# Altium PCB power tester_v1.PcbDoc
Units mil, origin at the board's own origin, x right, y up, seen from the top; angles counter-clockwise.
Board outline 3937.01 x 5944.88 mil, 2 copper layers (Top Layer, Bottom Layer); 152 components, 159 nets, 630 pads, 0 vias.
Unrouted connection lines stored in the file: 446.
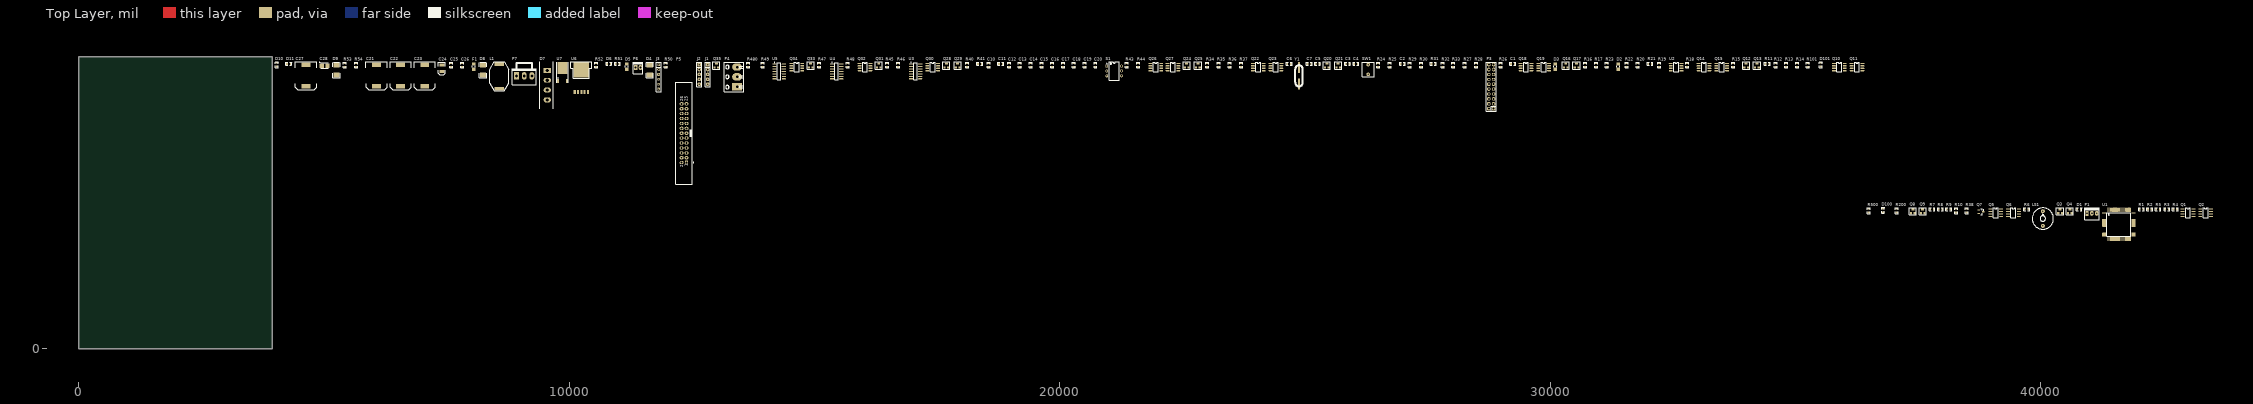
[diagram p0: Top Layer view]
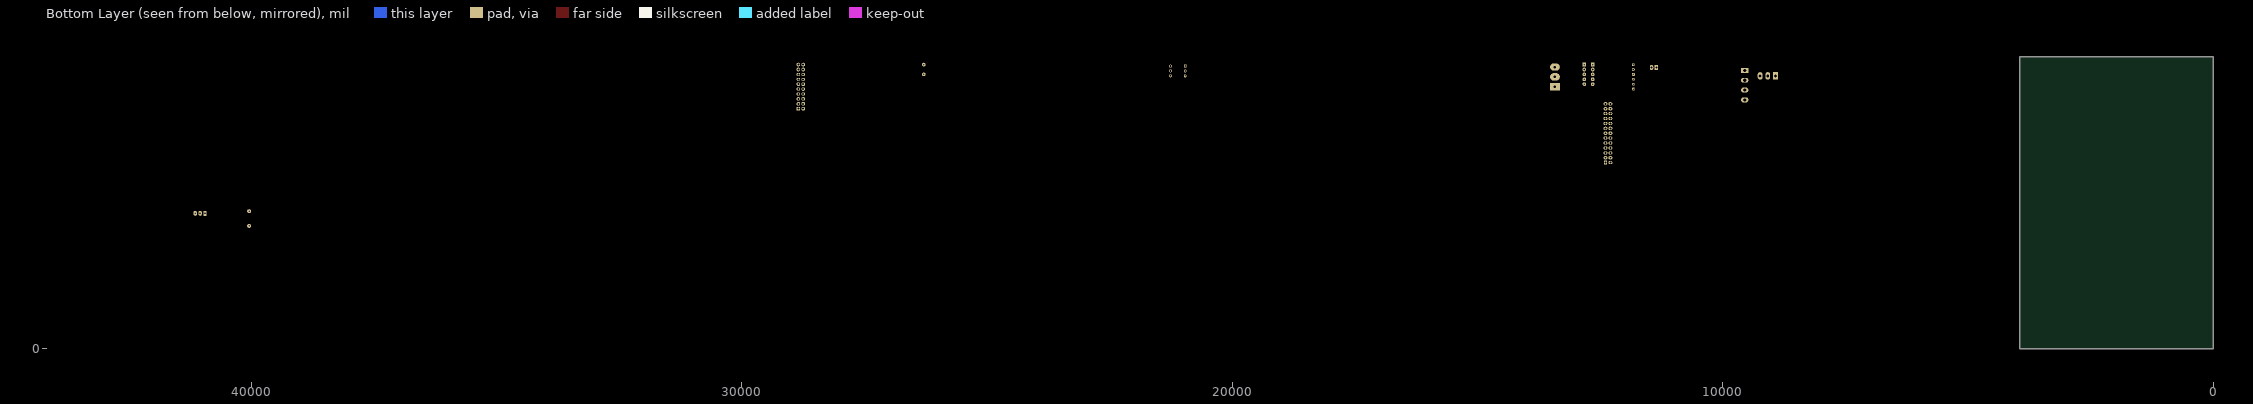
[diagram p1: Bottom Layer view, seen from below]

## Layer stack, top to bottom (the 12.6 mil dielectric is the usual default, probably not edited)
Top Solder: solder mask 0.4, Solder Resist, Dk 3.5
Top Layer: signal copper 1.4
Dielectric1: dielectric 12.6, FR-4, Dk 4.8
Bottom Layer: signal copper 1.4
Bottom Solder: solder mask 0.4, Solder Resist, Dk 3.5

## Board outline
0,0 0,5944.88 3937.01,5944.88 3937.01,0

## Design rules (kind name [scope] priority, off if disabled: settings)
Clearance Clearance_1 [(InNet('GND') OR InNet('SGND')) vs (InNet('GND') OR InNet('SGND'))] p1: gap=0
Clearance [All] p2: gap=7.5
ComponentClearance [All] p1 off: gap=10 collisioncheckmode=3 verticalgap=10 showdistances=FALSE
Height [All] p1 off: minheight=0 maxheight=1000 prefheight=500
HoleSize [All] p1 off: absolutevalues=TRUE maxlimit=100 minlimit=1 maxpercent=80.000 minpercent=20.000
HoleToHoleClearance [All] p1 off: gap=10 allowstackedmicrovias=TRUE
LayerPairs [All] p1 off: enforce=TRUE
MinimumSolderMaskSliver [All] p1 off: minsoldermaskwidth=10
NetAntennae [All] p1 off: netantennaetolerance=0
PolygonConnect [All] p1: connectstyle=Direct reliefconductorwidth=10 reliefentries=4 polygonreliefangle="90 Angle" airgapwidth=10
RoutingVias [All] p1: holewidth=28 width=50 viastyle="Through Hole" minholewidth=11 minwidth=30 maxholewidth=50 maxwidth=100
ShortCircuit [(InNet('GND') OR InNet('SGND')) vs (InNet('GND') OR InNet('SGND'))] p1: allowed=TRUE
SilkToSilkClearance [All] p1 off: silktosilkclearance=10
SilkToSolderMaskClearance [IsPad] p1 off: minsilkscreentomaskgap=10 clearancetoexposedcopper=TRUE
SolderMaskExpansion [All] p1: expansion=4
Width [All] p1: maxlimit=200 minlimit=10 preferedwidth=40
20 further rules are at their usual default settings.

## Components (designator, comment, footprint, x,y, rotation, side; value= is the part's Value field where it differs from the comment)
C1 "10nF" 0603BIG 29240,5810 r0 top
C2 "1nF" 0603BIG 26990,5810 r0 top
C3 "10uF" 0603BIG 25870,5810 r0 top
C4 "10uF" 0603BIG 26040,5810 r0 top
C5 "10uF" 0603BIG 25260,5810 r0 top
C6 "10pF" 0603BIG 24680,5810 r0 top
C7 "10pF" 0603BIG 25090,5810 r0 top
C10 "100nF" 0603BIG 18550,5780 r90 top
C11 "100nF" 0603BIG 18800,5810 r0 top
C12 "100nF" 0603BIG 18970,5780 r90 top
C13 "100nF" 0603BIG 19190,5780 r90 top
C14 "100nF" 0603BIG 19410,5780 r90 top
C15 "100nF" 0603BIG 19630,5780 r90 top
C16 "100nF" 0603BIG 19850,5780 r90 top
C17 "100nF" 0603BIG 20070,5780 r90 top
C18 "100nF" 0603BIG 20290,5780 r90 top
C19 "100nF" 0603BIG 20510,5780 r90 top
C20 "100nF" 0603BIG 20730,5780 r90 top
C21 "470uf" CAP-SMD-HV2 6070,5350 r90 top
C22 "470uf" CAP-SMD-HV2 6560,5350 r90 top
C23 "470uf" CAP-SMD-HV2 7050,5350 r90 top
C24 "220uf" 1210-C 7400,5650 r0 top
C25 "100n" 0603big 7590,5780 r90 top
C26 "10n" 0603big 7820,5780 r90 top
C27 "220U-50V" CAP-SMD-HV2 4630,5350 r90 top
C28 "100u 10V" CAP_TANTAL_B 5010,5770 r0 top
D1 "LED" 0805-d1 40750,2840 r0 top
D2 "D Zener" 8-1206 31390,5750 r90 top
D3 "D Zener" 8-1206 30110,5750 r90 top
D4 "DIODE" ss14 11640,5580 r90 top
D5 "D Zener" 8-1206 11170,5750 r90 top
D6 "LED" 0805-2D 10770,5810 r0 top
D7 "BRIDGE" BRG5A 9550,5070 r0 top
D8 "50SQ080" SS14 8240,5580 r90 top
D9 "SS16" SS14 5250,5580 r90 top
D10 "LED" 0805-D1 4030,5750 r90 top
D11 "LED" 0805-d1 4240,5810 r0 top
D100 "LED" 0805-d1 36790,2780 r90 top
D101 "LED" 0805-d1 35520,5750 r90 top
F1 "FUSE" 8-1206 8050,5750 r90 top
J1 "CON5" SIP5 12820,5590 r90 top
J2 "CON5" SIP5 12650,5590 r90 top
J3 "CON6" SIP6 11820,5540 r90 top
L1 "22UH 5A" "self smd" 8570,5800 r90 top
LS1 "Buzzer" Buzzer 40050,2650 r0 top
P1 "Header 3" mokhaberati3PIN 40900,2630 r0 top
P3 "Header 10X2" IDC20 28850,4890 r90 top
P4 "Header 3" "PHONIX 3" 13420,5540 r90 top
P5 "Header 13X2" 918526x904 12340,4390 r90 top
P6 "Header 2" mokhaberati 11500,5840 r0 top
P7 "Header 3" SIP3-155-la 9080,5560 r0 top
Q1 "IRF9310" so-8 43010,2770 r0 top
Q2 "IRF9310" so-8 43370,2770 r0 top
Q3 "2N7002" SOT-23 40400,2800 r0 top
Q4 "2N7002" SOT-23 40600,2800 r0 top
Q5 "IRF9310" so-8 39090,2770 r0 top
Q6 "IRF9310" so-8 39450,2770 r0 top
Q7 "2N2222" SOT23_M 38790,2790 r0 top
Q8 "2N7002" SOT-23 37400,2800 r0 top
Q9 "2N7002" SOT-23 37600,2800 r0 top
Q10 "IRF9310" so-8 35900,5740 r0 top
Q11 "IRF9310" so-8 36260,5740 r0 top
Q12 "2N7002" SOT-23 34000,5770 r0 top
Q13 "2N7002" SOT-23 34220,5770 r0 top
Q14 "IRF9310" so-8 33140,5740 r0 top
Q15 "IRF9310" so-8 33500,5740 r0 top
Q16 "2N7002" SOT-23 30320,5770 r0 top
Q17 "2N7002" SOT-23 30540,5770 r0 top
Q18 "IRF9310" so-8 29510,5740 r0 top
Q19 "IRF9310" so-8 29870,5740 r0 top
Q20 "2N7002" SOT-23 25450,5770 r0 top
Q21 "2N7002" SOT-23 25680,5770 r0 top
Q22 "IRF9310" so-8 24050,5740 r0 top
Q23 "IRF9310" so-8 24410,5740 r0 top
Q24 "2N7002" SOT-23 22590,5770 r0 top
Q25 "2N7002" SOT-23 22820,5770 r0 top
Q26 "IRF9310" so-8 21960,5740 r0 top
Q27 "IRF9310" so-8 22310,5740 r0 top
Q28 "2N7002" SOT-23 17690,5770 r0 top
Q29 "2N7002" SOT-23 17920,5770 r0 top
Q30 "IRF9310" so-8 17410,5740 r0 top
Q31 "2N7002" SOT-23 16310,5770 r0 top
Q32 "IRF9310" so-8 16030,5740 r0 top
Q33 "2N7002" SOT-23 14920,5770 r0 top
Q34 "IRF9310" so-8 14640,5740 r0 top
Q35 "2N7002" SOT-23 13000,5770 r0 top
R1 "330" 0603BIG 42060,2840 r0 top
R2 "330" 0603BIG 42230,2840 r0 top
R3 "10k" 0603BIG 42580,2840 r0 top
R4 "10k" 0603BIG 42750,2840 r0 top
R5 "1K" 0603BIG 42400,2840 r0 top
R6 "500" 0603BIG 39720,2840 r0 top
R7 "330" 0603BIG 37790,2840 r0 top
R8 "330" 0603BIG 37960,2840 r0 top
R9 "10k" 0603BIG 38130,2840 r0 top
R10 "10k" 0603BIG 38280,2810 r90 top
R11 "330" 0603BIG 34430,5810 r0 top
R12 "330" 0603BIG 34600,5780 r90 top
R13 "10k" 0603BIG 34820,5780 r90 top
R14 "10k" 0603BIG 35040,5780 r90 top
R15 "820" 0603BIG 33740,5780 r90 top
R16 "330" 0603BIG 30720,5780 r90 top
R17 "330" 0603BIG 30940,5780 r90 top
R18 "1K" 0603BIG 32800,5780 r90 top
R19 "1K" 0603BIG 32230,5780 r90 top
R20 "10k" 0603BIG 31790,5780 r90 top
R21 "10k" 0603BIG 32040,5810 r0 top
R22 "1k" 0603big 31560,5780 r90 top
R23 "1K" 0603BIG 31160,5780 r90 top
R24 "330" 0603BIG 26500,5780 r90 top
R25 "330" 0603BIG 26730,5780 r90 top
R26 "1.5K" 0603BIG 28990,5780 r90 top
R27 "10k" 0603BIG 28260,5780 r90 top
R28 "10k" 0603BIG 28490,5780 r90 top
R29 "100K" 0603BIG 27140,5780 r90 top
R30 "100K" 0603BIG 27370,5780 r90 top
R31 "100K" 0603BIG 27620,5810 r0 top
R32 "100K" 0603BIG 27810,5780 r90 top
R33 "1K" 0603BIG 28030,5780 r90 top
R34 "330" 0603BIG 23010,5780 r90 top
R35 "330" 0603BIG 23240,5780 r90 top
R36 "10k" 0603BIG 23470,5780 r90 top
R37 "10k" 0603BIG 23700,5780 r90 top
R38 "1K" 0603BIG 38500,2810 r90 top
R40 "330" 0603BIG 18110,5780 r90 top
R41 "330" 0603BIG 18370,5810 r0 top
R43 "10k" 0603BIG 21370,5780 r90 top
R44 "10k" 0603BIG 21600,5780 r90 top
R45 "330" 0603BIG 16480,5780 r90 top
R46 "10k" 0603BIG 16710,5780 r90 top
R47 "330" 0603BIG 15100,5780 r90 top
R48 "10k" 0603BIG 15680,5780 r90 top
R49 "10k" 0603BIG 13940,5780 r90 top
R50 "10k" 0603BIG 11970,5780 r90 top
R51 "1k" 0603BIG 10980,5810 r0 top
R52 "330" 0603BIG 10550,5780 r90 top
R53 "R" 0603big 5420,5780 r90 top
R54 "R" 0603big 5650,5780 r90 top
R101 "1K" 0603BIG 35260,5780 r90 top
R200 "1K" 0603BIG 37070,2810 r90 top
R480 "330" 0603BIG 13650,5780 r90 top
R500 "1K" 0603BIG 36500,2810 r90 top
S1 "SW DIP-3" DIP-6 21110,5660 r0 top
SW1 "P.B" SW_200 26290,5790 r0 top
U1 "AT91SAM7X256-AU" LQFP100 41600,2530 r0 top
U2 "LM258" so-8 32570,5740 r0 top
U3 "SN7404N" D014_N 17060,5650 r0 top
U4 "SN7404N" D014_N 15450,5650 r0 top
U5 "SN7404N" D014_N 14280,5650 r0 top
U6 "LM2576-5v" LM2576-SMD 10110,5230 r0 top
U7 "LD1086DT33" 7805_SMD 9860,5590 r0 top
Y1 "18.432 MHZ" NIRAXTAL-smd 24880,5560 r90 top

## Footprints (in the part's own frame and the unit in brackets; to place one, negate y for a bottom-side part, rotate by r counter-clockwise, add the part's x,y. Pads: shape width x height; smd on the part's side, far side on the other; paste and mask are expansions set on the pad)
8-1206 [mm] "Chip Resistor; Body 3.1 x 1.6 mm (LxW typ)"
  rect 1.6x1.8 smd: 1(-1.4,0) 2(1.4,0)
  silkscreen extent -0.3,-0.8 0.3,0.8
0603BIG [mm]
  rect 0.9x1.4 smd: 1(0.965,0) 2(-0.965,0)
  silkscreen extent -1.48,-0.77 1.49,0.77
0603big [mm]
  rect 0.9x1.4 smd: 1(0.965,0) 2(-0.965,0)
  silkscreen extent -1.48,-0.77 1.49,0.77
0805-2D [mm]
  rect 0.9x1.4 smd: A(0,0) K(1.93,0)
  silkscreen extent -0.52,-0.77 2.45,0.77
0805-d1 [mm]
  rect 0.9x1.4 smd: A(0,0) K(1.93,0)
  silkscreen extent -0.52,-0.77 2.45,0.77
0805-D1 [mm]
  rect 0.9x1.4 smd: A(0,0) K(1.93,0)
  silkscreen extent -0.52,-0.77 2.45,0.77
1210-C [mil]
  rect 100x60 smd: 1(0,0) 2(0,135)
  silkscreen extent -70,-66 70,185
7805_SMD [mm]
  rect 1x2.1 smd: 1(2.285,-3.375) 2(-2.285,-3.375)
  rect 5.4x6.2 smd: 3(0,3.375)
  silkscreen extent -3.08,-4.33 3.08,6.37
918526x904 [mm] "Connector; IDC, Thru-Hole; 26 Position; Vertical; Pitch 2.54 mm; Body 52.60 x 8.5 x 25.75 mm (LxWxH), Locking levers"
  rect 2.032x1.65 hole 1: 1(-15.24,-1.27)
  oval 1.65x2.032 hole 1: 2(-15.24,1.27) 3(-12.7,-1.27) 4(-12.7,1.27) 5(-10.16,-1.27) 6(-10.16,1.27) 7(-7.62,-1.27) 8(-7.62,1.27) 9(-5.08,-1.27) 10(-5.08,1.27) 11(-2.54,-1.27) 12(-2.54,1.27) 13(0,-1.27) 14(0,1.27) 15(2.54,-1.27) 16(2.54,1.27) 17(5.08,-1.27) 18(5.08,1.27) 19(7.62,-1.27) 20(7.62,1.27) 21(10.16,-1.27) 22(10.16,1.27) 23(12.7,-1.27) 24(12.7,1.27) 25(15.24,-1.27) 26(15.24,1.27)
  silkscreen extent -26.3,-5.03 26.3,4.25
BRG5A [mil]
  oval 150x100 hole 65: AC1(0,200) AC2(0,400) DC-(0,0)
  rect 150x100 hole 65: DC+(0,600)
  silkscreen extent -157,-177 126,773
Buzzer [mil]
  round 80 hole 27.56: 1A(0,150) 2A(0,-150)
  silkscreen extent -216,-216 217,216
CAP-SMD-HV2 [mil]
  rect 90x180 smd: 1(0,0) 2(433.07,0)
  silkscreen extent -70,-217 493,217
CAP_TANTAL_B [mm] "Molded Capacitor, 2-Leads, Body 3.50x2.80mm, IPC Medium Density"
  rect 2.2x2.3 smd: 1(-1.5,0) 2(1.5,0)
  silkscreen extent -2.67,-1.5 1.9,1.82, body extent -1.85,-1.5 1.85,1.5, height 1.9
D014_N [mm] "SOIC, 14-Leads, Body 8.7x3.9mm, Pitch 1.27mm, IPC Medium Density"
  oval 2.2x0.6 smd: 1(-2.4,3.81) 2(-2.4,2.54) 3(-2.4,1.27) 4(-2.4,0) 5(-2.4,-1.27) 6(-2.4,-2.54) 7(-2.4,-3.81) 8(2.4,-3.81) 9(2.4,-2.54) 10(2.4,-1.27) 11(2.4,0) 12(2.4,1.27) 13(2.4,2.54) 14(2.4,3.81)
  silkscreen extent -2.52,-4.4 0.9,4.78, body extent -1.95,-4.33 1.95,4.33, height 1.75
DIP-6 [mm] "DIP; 6 Leads; Row Spacing 7.62 mm; Pitch 2.54 mm"
  rect 1.5x1.5 hole 0.9: 1(-3.81,2.54)
  round 1.5 hole 0.9: 2(-3.81,0) 3(-3.81,-2.54) 4(3.81,-2.54) 5(3.81,0) 6(3.81,2.54)
  silkscreen extent -3.93,-4.7 2.65,4.7, body extent -3.55,-4.7 3.55,4.7, height 5.46
IDC20 [mil]
  rect 75x75 hole 41: 1(0,0)
  round 75 hole 41: 2(0,100) 3(100,0) 4(100,100) 5(200,0) 6(200,100) 11(500,0) 12(500,100) 17(800,0) 18(800,100) 19(900,0) 20(900,100)
  oval 65x75 hole 41: 7(300,0) 9(400,0)
  oval 70x75 hole 41: 8(300,100) 10(400,100)
  oval 62x75 hole 41: 13(600,0) 14(600,100) 15(700,0) 16(700,100)
  silkscreen extent -50,-50 950,150
LM2576-SMD [mm]
  rect 1.07x2.16 smd: FB(5.1,0) GND(3.4,0) O\N\/OFF(6.8,0) OUT(1.7,0) VIN(0,0)
  rect 8x8 smd: GND(3.4,11.5)
  silkscreen extent -2,7.18 8.8,15.67
LQFP100 [mm]
  rect 2.1x0.3 smd: 1(-7.6,6)
  oval 2.1x0.3 smd: 2(-7.6,5.5) 3(-7.6,5) 4(-7.6,4.5) 5(-7.6,4) 6(-7.6,3.5) 7(-7.6,3) 8(-7.6,2.5) 9(-7.6,2) 10(-7.6,1.5) 11(-7.6,1) 12(-7.6,0.5) 13(-7.6,0) 14(-7.6,-0.5) 15(-7.6,-1) 16(-7.6,-1.5) 17(-7.6,-2) 18(-7.6,-2.5) 19(-7.6,-3) 20(-7.6,-3.5) 21(-7.6,-4) 22(-7.6,-4.5) 23(-7.6,-5) 24(-7.6,-5.5) 25(-7.6,-6) 51(7.6,-6) 52(7.6,-5.5) 53(7.6,-5) 54(7.6,-4.5) 55(7.6,-4) 56(7.6,-3.5) 57(7.6,-3) 58(7.6,-2.5) 59(7.6,-2) 60(7.6,-1.5) 61(7.6,-1) 62(7.6,-0.5) 63(7.6,0) 64(7.6,0.5) 65(7.6,1) 66(7.6,1.5) 67(7.6,2) 68(7.6,2.5) 69(7.6,3) 70(7.6,3.5) 71(7.6,4) 72(7.6,4.5) 73(7.6,5) 74(7.6,5.5) 75(7.6,6)
  oval 0.3x2.1 smd: 26(-6,-7.6) 27(-5.5,-7.6) 28(-5,-7.6) 29(-4.5,-7.6) 30(-4,-7.6) 31(-3.5,-7.6) 32(-3,-7.6) 33(-2.5,-7.6) 34(-2,-7.6) 35(-1.5,-7.6) 36(-1,-7.6) 37(-0.5,-7.6) 38(0,-7.6) 39(0.5,-7.6) 40(1,-7.6) 41(1.5,-7.6) 42(2,-7.6) 43(2.5,-7.6) 44(3,-7.6) 45(3.5,-7.6) 46(4,-7.6) 47(4.5,-7.6) 48(5,-7.6) 49(5.5,-7.6) 50(6,-7.6) 76(6,7.6) 77(5.5,7.6) 78(5,7.6) 79(4.5,7.6) 80(4,7.6) 81(3.5,7.6) 82(3,7.6) 83(2.5,7.6) 84(2,7.6) 85(1.5,7.6) 86(1,7.6) 87(0.5,7.6) 88(0,7.6) 89(-0.5,7.6) 90(-1,7.6) 91(-1.5,7.6) 92(-2,7.6) 93(-2.5,7.6) 94(-3,7.6) 95(-3.5,7.6) 96(-4,7.6) 97(-4.5,7.6) 98(-5,7.6) 99(-5.5,7.6) 100(-6,7.6)
  silkscreen extent -6.15,-6.15 6.15,6.15
mokhaberati [mm] "Connector; Header; 2 Position"
  rect 1.8x2.5 hole 0.9: 1(-3.81,-2.794)
  oval 1.8x2.5 hole 0.9: 2(-1.27,-2.794)
  silkscreen extent -5.09,-6 0,0
mokhaberati3PIN [mm] "Connector; Header; 2 Position"
  rect 1.8x2.5 hole 0.9: 1(1.27,3.206)
  oval 1.8x2.5 hole 0.9: 2(3.81,3.206) 3(6.35,3.206)
  silkscreen extent -0.01,0 7.62,6
NIRAXTAL-smd [mil] "Connector; Header; 3 Position"
  rect 220.47x40 smd: 1(-168,0) 2(168,0)
  silkscreen extent -225,-90 225,90
"PHONIX 3" [mil]
  rect 150x200 hole 50: 1(-200,0)
  oval 150x200 hole 50: 2(0,0) 3(200,0)
  silkscreen extent -300,-138 300,257
"self smd" [mm]
  rect 2x5 smd: 1(0,0) 2(-12.8,0)
  silkscreen extent -13.9,-5 1.1,5
SIP3-155-la [mil]
  rect 100x150 hole 60: 1(-155,0)
  oval 100x150 hole 60: 2(0,0) 3(155,0)
  silkscreen extent -245,-180 250,265
SIP5 [mil]
  rect 75x75 hole 32: 1(200,0)
  round 75 hole 32: 2(100,0) 3(0,0) 4(-100,0) 5(-200,0)
  silkscreen extent -250,-50 250,50
SIP6 [mil]
  rect 50x50 hole 32: 1(250,0)
  round 55 hole 32: 2(150,0) 4(-50,0)
  round 65 hole 32: 3(50,0)
  oval 55x50 hole 32: 5(-150,0)
  oval 65x50 hole 32: 6(-250,0)
  silkscreen extent -300,-50 300,50
so-8 [mil]
  oval 80x24 smd: 1(-110,75) 2(-110,25) 3(-110,-25) 4(-110,-75) 5(110,-75) 6(110,-25) 7(110,25) 8(110,75)
  silkscreen extent -50,-100 50,100
SOT23_M [mm] "SOT23, 3-Leads, Body 2.9x1.3mm, Pitch 0.95mm, Lead Span 2.3mm - Reverse Pinning, IPC Low Density"
  rect 1.45x0.6 smd: 1(1.175,0) 2(-1.175,-0.95) 3(-1.175,0.95)
  silkscreen extent -0.1,-1.5 1.48,1.5, body extent -0.7,-1.5 0.7,1.5, height 1.1
SOT-23 [mil]
  rect 45x45 smd: 1(-38,-40) 3(38,-40)
  rect 60x45 smd: 2(0,40)
  silkscreen extent -72,-72 72,73
ss14 [mm]
  rect 2.54x3.175 smd: A(0,0) K(5,0)
  silkscreen extent -1.55,-1.91 6.62,1.91
SS14 [mm]
  rect 2.54x3.175 smd: A(0,0) K(5,0)
  silkscreen extent -1.55,-1.91 6.62,1.91
SW_200 [mil]
  round 75 hole 28: 1(0,0) 2(0,-200)
  silkscreen extent -125,-250 125,50

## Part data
C1 C2 C6 C7 C10 C11 C12 C13 C14 C15 C16 C17 C18 C19 C20: library part Cap, "Capacitor"
C3 C5: library part "Cap Pol1", "10v"
C4: library part "Cap Pol1", "Polarized Capacitor (Radial)"
C21 C22 C23 C24: library part CAP_Dup1
C25 C26: library part C
C27 C28: library part CAP
D2 D3 D5: "Zener Diode"
D4: library part DIODE_0
D8 D9: library part DIODE
L1: library part L
LS1: "Magnetic Transducer Buzzer"
P1 P4 P7: "Header, 3-Pin"
P3: "Header, 10-Pin, Dual row"
P5: "Header, 13-Pin, Dual row"
P6: "Header, 2-Pin"
Q1 Q2 Q5 Q6 Q10 Q11 Q14 Q15 Q18 Q19 Q22 Q23 Q26 Q27 Q30 Q32 Q34: library part IRF9310_0
Q3 Q4 Q8 Q9 Q12 Q13 Q16 Q17 Q20 Q21 Q24 Q25 Q28 Q29 Q31 Q33 Q35: library part "MOSFET N"
Q7: "General Purpose Transistor NPN Silicon"
R1 R2 R3 R4 R7 R8 R9 R10 R11 R12 R13 R14 R16 R17 R20 R21 R24 R25 R27 R28 R34 R35 R36 R37 R40 R41 R43 R44 R45 R46 R47 R48 R49 R50 R480: library part R_Dup4
R5 R6 R18 R22 R23 R26 R29 R30 R31 R32 R33 R38 R52 R101 R200 R500: library part Res1, "Resistor"
R15 R19 R51: library part R
S1: "DIP Switch, 3 Position, SPST"
SW1: library part Push-Button
U1: "AT91 ARM Thumb-based 32-bit Microcontroller, 256KB Flash, 64KB SRAM, E-MAC, CAN, 100-Pin LQFP, Industrial Grade (-40°C to 85°C), Pb-Free"
U2: library part OP279GS, "Rail-to-Rail High-Output-Current Operational Amplifier"
U3 U4 U5: "Hex Inverter"
U6: library part LM2576/TO_0
U7: library part LT1086-12/TO
Y1: library part XTAL, "Crystal Oscillator"

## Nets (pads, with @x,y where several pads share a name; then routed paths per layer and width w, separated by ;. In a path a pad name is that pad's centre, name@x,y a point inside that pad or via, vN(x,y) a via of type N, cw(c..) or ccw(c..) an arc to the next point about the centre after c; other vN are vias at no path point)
#CNT-CH1: R1.1 U1.9
#CNT-CH2: R7.1 U1.10
#CNT-CH3: R11.1 U1.11
#CNT-CH4: R16.1 U1.12
#CNT-CH5: R24.1 U1.13
#CNT-CH6: R34.1 U1.14
#CNT-CH7: R40.1 U1.18
#CNT-CH8: R45.1 U1.19
#CNT-CH9: R47.1 U1.20
#CNT-CH10: R2.1 U1.21
#CNT-CH11: R8.1 U1.22
#CNT-CH12: R12.1 U1.23
#CNT-CH13: R17.1 U1.24
#CNT-CH14: R25.1 U1.25
#CNT-CH15: R35.1 U1.26
#CNT-CH16: R41.1 U1.27
#SHORT.CR: R480.1 U1.80
+3.3V: C3.1 C10.2 C11.2 C12.2 C13.2 C14.2 C19.2 C20.2 C24.1 C25.1 C26.1 J3.1 P3.1 P3.2 R29.2 R30.2 R31.2 R32.2 R33.2 R53.1 R200.1 S1.1 S1.2 S1.3 U1.1 U1.8 U1.17 U1.33 U1.48 U1.61 U1.84 U1.95 U1.100 U7.3
"B_CLOCK TEST_G": P5.16 U3.10
B_G_LED_CH1: P5.1 U5.2
B_G_LED_CH2: P5.3 U5.4
B_G_LED_CH3: P5.5 U5.6
B_G_LED_CH4: P5.6 U5.8
B_G_LED_CH5: P5.4 U5.10
B_G_LED_CH6: P5.2 U5.12
B_G_LED_CH7: P5.7 U4.2
B_G_LED_CH8: P5.9 U4.4
B_G_LED_CH9: P5.11 U4.6
B_G_LED_CH10: P5.12 U4.8
B_G_LED_CH11: P5.10 U4.10
B_G_LED_CH12: P5.8 U4.12
B_G_LED_CH13: P5.13 U3.2
B_G_LED_CH14: P5.15 U3.4
B_G_LED_CH15: P5.17 U3.6
B_G_LED_CH16: P5.18 U3.8
"B_VOLTAGE TEST _G": P5.14 U3.12
BUZZER: R38.1 U1.35
CH1: Q1.1 Q1.2 Q1.3 R3.1
CH2: Q5.1 Q5.2 Q5.3 R9.1
CH3: Q10.1 Q10.2 Q10.3 R13.1
CH4: Q14.1 Q14.2 Q14.3 R20.1
CH5: Q18.1 Q18.2 Q18.3 R27.1
CH6: Q22.1 Q22.2 Q22.3 R36.1
CH7: Q26.1 Q26.2 Q26.3 R43.1
CH8: Q30.1 Q30.2 Q30.3 R46.1
CH9: Q32.1 Q32.2 Q32.3 R48.1
CH10: Q2.1 Q2.2 Q2.3 R4.1
CH11: Q6.1 Q6.2 Q6.3 R10.1
CH12: Q11.1 Q11.2 Q11.3 R14.1
CH13: Q15.1 Q15.2 Q15.3 R21.1
CH14: Q19.1 Q19.2 Q19.3 R28.1
CH15: Q23.1 Q23.2 Q23.3 R37.1
CH16: Q27.1 Q27.2 Q27.3 R44.1
"CLOCK COMMAND OUT": D1.K P1.1 Q7.3
"CLOCK IN": P1.3 R19.1
"CLOCK SAMPLE": D3.2 R22.2 U1.5
"CLOCK TEST_G": U1.54 U3.11
"CURRENT SAMPEL": J3.3 U1.3
DLED1: R500.2 U1.38
DLED2: R101.2 U1.39
ERASE: S1.5 U1.92
G_LED_CH1: U1.75 U5.1
G_LED_CH2: U1.74 U5.3
G_LED_CH3: U1.73 U5.5
G_LED_CH4: U1.72 U5.9
G_LED_CH5: U1.71 U5.11
G_LED_CH6: U1.70 U5.13
G_LED_CH7: U1.69 U4.1
G_LED_CH8: U1.67 U4.3
G_LED_CH9: U1.66 U4.5
G_LED_CH10: U1.65 U4.9
G_LED_CH11: U1.64 U4.11
G_LED_CH12: U1.63 U4.13
G_LED_CH13: U1.60 U3.1
G_LED_CH14: U1.59 U3.3
G_LED_CH15: U1.56 U3.5
G_LED_CH16: U1.55 U3.9
GND: C21.2 C22.2 C23.2 C24.2 C25.2 C26.2 C27.2 C28.2 D2.1 D3.1 D4.A D7.DC- D9.A D10.K D11.K P4.3 P6.1 Q3.3 Q4.3 Q8.3 Q9.3 Q12.3 Q13.3 Q16.3 Q17.3 Q20.3 Q21.3 Q24.3 Q25.3 Q28.3 Q29.3 Q31.3 Q33.3 Q35.3 R23.1 R50.2 U2.3 U2.4 U2.5 U6.GND U6.O\N\/OFF U7.2
JTAGSEL: S1.4 U1.77
LOAD: J2.1 J2.2 J2.3 J2.4 J2.5 P4.1 Q34.1 Q34.2 Q34.3 R49.1
NetC1_2: C1.2 R26.1
NetC2_2: C2.2 R26.2 U1.99
NetC21_1: C21.1 C22.1 C23.1 D8.A F1.2 P6.2 R51.2 R52.2
NetC27_1: C27.1 D8.K U6.VIN
NetD1_A: D1.A R5.1
NetD5_2: D5.2 R52.1
NetD6_A: D6.A D7.DC+ F1.1
NetD6_K: D6.K R51.1
NetD7_AC1: D7.AC1 P7.1
NetD7_AC2: D7.AC2 P7.3
NetD9_K: D9.K L1.1 U6.OUT
NetD10_A: D10.A R53.2
NetD11_A: D11.A R54.2
NetD100_A: D100.A R500.1
NetD101_A: D101.A R101.1
NetLS1_2A: LS1.2A
NetQ1_4: Q1.4 Q3.2 R3.2
NetQ2_4: Q2.4 Q4.2 R4.2
NetQ3_1: Q3.1 R1.2
NetQ4_1: Q4.1 R2.2
NetQ5_4: Q5.4 Q8.2 R9.2
NetQ6_4: Q6.4 Q9.2 R10.2
NetQ7_2: Q7.2 R6.2
NetQ8_1: Q8.1 R7.2
NetQ9_1: Q9.1 R8.2
NetQ10_4: Q10.4 Q12.2 R13.2
NetQ11_4: Q11.4 Q13.2 R14.2
NetQ12_1: Q12.1 R11.2
NetQ13_1: Q13.1 R12.2
NetQ14_4: Q14.4 Q16.2 R20.2
NetQ15_4: Q15.4 Q17.2 R21.2
NetQ16_1: Q16.1 R16.2
NetQ17_1: Q17.1 R17.2
NetQ18_4: Q18.4 Q20.2 R27.2
NetQ19_4: Q19.4 Q21.2 R28.2
NetQ20_1: Q20.1 R24.2
NetQ21_1: Q21.1 R25.2
NetQ22_4: Q22.4 Q24.2 R36.2
NetQ23_4: Q23.4 Q25.2 R37.2
NetQ24_1: Q24.1 R34.2
NetQ25_1: Q25.1 R35.2
NetQ26_4: Q26.4 Q28.2 R43.2
NetQ27_4: Q27.4 Q29.2 R44.2
NetQ28_1: Q28.1 R40.2
NetQ29_1: Q29.1 R41.2
NetQ30_4: Q30.4 Q31.2 R46.2
NetQ31_1: Q31.1 R45.2
NetQ32_4: Q32.4 Q33.2 R48.2
NetQ33_1: Q33.1 R47.2
NetQ34_4: Q34.4 Q35.2 R49.2
NetQ35_1: Q35.1 R480.2
NetQ36_2: R38.2
NetR15_1: R15.1 R19.2 U2.2
NetR15_2: R15.2 R22.1 U2.1
NetU2_6: U2.6 U2.7
NRST: C4.1 P3.15 R33.1 SW1.2 U1.57
OUT1: D4.K J1.1 J1.2 J1.3 J1.4 J1.5 Q1.5 Q1.6 Q1.7 Q1.8 Q2.5 Q2.6 Q2.7 Q2.8 Q5.5 Q5.6 Q5.7 Q5.8 Q6.5 Q6.6 Q6.7 Q6.8 Q10.5 Q10.6 Q10.7 Q10.8 Q11.5 Q11.6 Q11.7 Q11.8 Q14.5 Q14.6 Q14.7 Q14.8 Q15.5 Q15.6 Q15.7 Q15.8 Q18.5 Q18.6 Q18.7 Q18.8 Q19.5 Q19.6 Q19.7 Q19.8 Q22.5 Q22.6 Q22.7 Q22.8 Q23.5 Q23.6 Q23.7 Q23.8 Q26.5 Q26.6 Q26.7 Q26.8 Q27.5 Q27.6 Q27.7 Q27.8 Q30.5 Q30.6 Q30.7 Q30.8 Q32.5 Q32.6 Q32.7 Q32.8 R18.2 R50.1
"OVER CURRENT": J3.4 U1.82
"POWER GOOD": D5.1 P5.19
RESET: J3.5 U1.85
SC-LOAD: P4.2 Q34.5 Q34.6 Q34.7 Q34.8
SGND: C1.1 C2.1 C3.2 C4.2 C5.2 C6.1 C7.1 C10.1 C11.1 C12.1 C13.1 C14.1 C15.1 C16.1 C17.1 C18.1 C19.1 C20.1 D100.K D101.K J3.6 P1.2 P3.4 P3.6 P3.8 P3.10 P3.12 P3.14 P3.16 P3.18 P3.20 P5.23 P5.24 P5.25 P5.26 Q7.1 SW1.1 U1.2 U1.16 U1.32 U1.52 U1.68 U1.83 U1.96 U3.7 U4.7 U5.7
"SHUT DOWN": J3.2 U1.81
START_SWITCH: P5.21 R200.2 U1.29
START_SWITCH_LED: P5.20 U1.30
TCK: P3.9 P3.11 R30.1 U1.79
TDI: P3.5 R32.1 U1.51
TDO: P3.13 R29.1 U1.76
TMS: P3.7 R31.1 U1.78
TST: U1.58
"UC CLOCK COMMAND": R6.1 U1.28
"USB DM": U1.93
"USB DP": U1.94
VCC: C28.1 L1.2 LS1.1A R5.2 R54.1 U2.8 U3.14 U4.14 U5.14 U6.FB U7.1
"VOLTAGE SAMPLE": D2.2 R18.1 R23.2 U1.4
"VOLTAGE TEST _G": U1.53 U3.13
"VOUT 1.8V": C5.1 C15.2 C16.2 C17.2 C18.2 U1.7 U1.15 U1.37 U1.62 U1.87
XIN: C6.2 U1.97 Y1.1
XOUT: C7.2 U1.98 Y1.2
pads on no net: P3.3 P3.17 P3.19 P5.22 P7.2 S1.6 U1.6 U1.31 U1.34 U1.36 U1.40 U1.41 U1.42 U1.43 U1.44 U1.45 U1.46 U1.47 U1.49 U1.50 U1.86 U1.88 U1.89 U1.90 U1.91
